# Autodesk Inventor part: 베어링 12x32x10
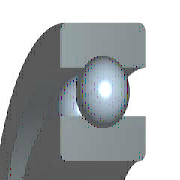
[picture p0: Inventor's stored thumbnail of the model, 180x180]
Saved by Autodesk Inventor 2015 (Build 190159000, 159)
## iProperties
IsCustomPart: 1
Created: 2012-02
Part Number: 베어링 12x32x10
Material: 강철, 연강
Description: 깊은 그루브 볼 베어링
Document SubType Name: Modeling
Standard: KS B 2023
Designer: test
Standards Organization: KS
Language: ko-KR
Size Designation: 6201 - 12 x 32 x 10
Categories: <MemberInstance><Categories><Category DisplayName="샤프트 부품" InternalName="7f7aeb1f-a693-4053-b835-cee3144e0d98" Mnemonic="SHFT"><Category DisplayName="베어링" Inter
Density: 1 g/cm^3
Appearance: 노란색
Author: test
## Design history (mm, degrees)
sketch "스케치" dims "d0" = 5.2 (= -0.26 x WD + 0.26 x BD)
  geometry: L1 (2.4, 11)-(7.6, 11); L2 (5, 11)-(5, 8.4); L3 (5, 11)-(5, 13.6); L4 (3.068, 9.26)-(0, 9.26); L5 (0, 6)-(10, 6); L6 (3.068, 12.74)-(0, 12.74); L7 (0, 16)-(10, 16); L8 (10, 6)-(10, 9.26); L9 (6.932, 9.26)-(10, 9.26); L10 (6.932, 12.74)-(10, 12.74); L11 (10, 16)-(10, 12.74); L12 (-1.4, 0)-(8.4, 0) reference; L13 (0, -0.3)-(0, 5.3) reference
  constraints: 22 end point, 4 point on line, 2 collinear, 2 perpendicular, 2 symmetric about line, 1 midpoint, 1 parallel, 14 other
  dimensions: "d9" = 12 diameter of L5 L12 (= WD); "d11" = 32 diameter of L7 L12 (= BD); "d12" = 10 distance between parallel lines of L8 L13 (= KB); "d13" = 18.52 diameter of L9 L12 (= 0.326 x BD + 0.674 x WD)
revolve "본체" stored, may be unused: angle "d6" = 90 deg
revolve "볼" stored, may be unused: angle "d7" = 90 deg
pattern_circular "IDS_ARRAYBALL[SIMPL:T]" dims angle "d3" = 360 deg
body "Solid1"
fillet "모깎기1" dims "d1" = 0.6 (= KRS)
other parameters: "WD" = 12 [user parameter; used in 5 equation terms], "BD" = 32 [user parameter; used in 5 equation terms], "KB" = 10 [user parameter; used in 1 equation term], "KRS" = 0.6 [user parameter; used in 1 equation term], "d4" = 0, "d5" = 0, "d8" = 0, "d14" = 0, "d15" = 0, "BBA" = 0 [user parameter], "BC0" = 3100000 [user parameter], "BC" = 6890000 [user parameter], "BR" = 16 (= 0.5 x BD) [user parameter], "WR" = 6 (= 0.5 x WD) [user parameter]
